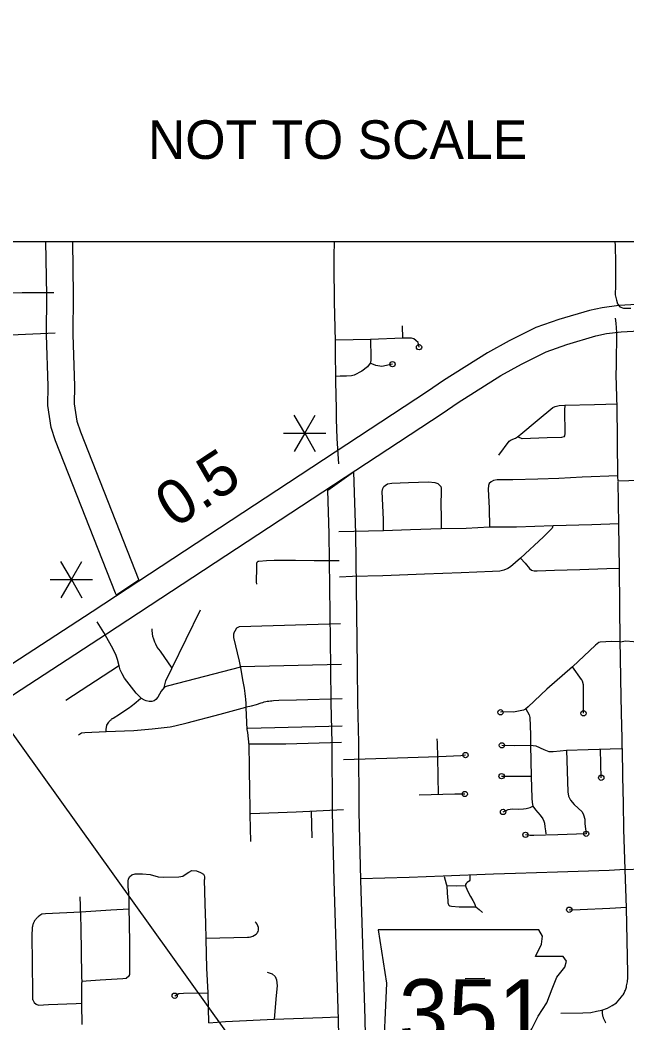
# Model space of a CAD drawing. Extents: x 309348 to 309445, y 336383 to 336484.
# Drawn here: x 309362.374 to 309364.99, y 336391.134 to 336395.46 of the extents above; entities that cross this region are included whole.
import ezdxf

# ---------------------------------------------------------------- set-up
doc = ezdxf.new("R2010")
doc.units = 0
doc.layers.add('R_Annotation', color=7, linetype='Continuous')
doc.layers.add('R_Border Notes', color=7, linetype='Continuous')

msp = doc.modelspace()

# ---------------------------------------------------------------- linework, layer by layer
at = {"layer": 'R_Annotation'}
for p, q in [((309363.601, 336393.6776), (309363.5555, 336393.7564)), ((309363.601, 336393.6776), (309363.6465, 336393.7564)), ((309363.5101, 336393.6776), (309363.601, 336393.6776)), ((309363.601, 336393.6776), (309363.5555, 336393.5989)), ((309363.601, 336393.6776), (309363.6919, 336393.6776)), ((309363.601, 336393.6776), (309363.6465, 336393.5989)), ((309362.5952, 336393.0464), (309362.5497, 336393.1252)), ((309362.5952, 336393.0464), (309362.6407, 336393.1252)), ((309362.5043, 336393.0464), (309362.5952, 336393.0464)), ((309362.5952, 336393.0464), (309362.5497, 336392.9677)), ((309362.5952, 336393.0464), (309362.6862, 336393.0464)), ((309362.5952, 336393.0464), (309362.6407, 336392.9677)), ((309362.8855, 336393.044), (309362.7898, 336392.9797))]:
    msp.add_line(p, q, dxfattribs=at)
for points in [[(309357.367, 336395.4603), (309360.1377, 336395.4603), (309363.8212, 336390.3132)], [(309362.7898, 336392.9797), (309362.7852, 336392.9884), (309362.5272, 336393.6448), (309362.5079, 336393.7026), (309362.4937, 336393.7978), (309362.4949, 336393.8807), (309362.4886, 336394.1021), (309362.4899, 336394.2732), (309362.4858, 336394.5049)], [(309362.5995, 336394.5049), (309362.6036, 336394.2737), (309362.6023, 336394.1033), (309362.6086, 336393.8815), (309362.6075, 336393.8054), (309362.6189, 336393.7292), (309362.6341, 336393.6835), (309362.8855, 336393.044)], [(309363.7324, 336394.1322), (309363.73, 336394.2449), (309363.7285, 336394.4017), (309363.7284, 336394.4416), (309363.7299, 336394.5049)], [(309364.9374, 336394.5049), (309364.9388, 336394.4861), (309364.941, 336394.414), (309364.9403, 336394.3153), (309364.9396, 336394.2748), (309364.9447, 336394.2513), (309364.9491, 336394.2358), (309364.9587, 336394.2233), (309364.9756, 336394.2174), (309364.983, 336394.2167), (309365.0066, 336394.2167)], [(309367.0035, 336394.3488), (309366.123, 336394.2935), (309364.9553, 336394.2289), (309364.883, 336394.2195), (309364.8281, 336394.2076), (309364.6962, 336394.1686), (309364.597, 336394.1336), (309364.4828, 336394.0765), (309364.3887, 336394.0246), (309364.2, 336393.9054), (309364.1306, 336393.8579), (309362.6846, 336392.9078), (309361.7768, 336392.3157)], [(309362.5204, 336394.2838), (309362.4556, 336394.2829), (309362.3833, 336394.2829), (309362.2884, 336394.2819), (309362.2282, 336394.2801)], [(309361.7768, 336392.3157), (309361.666, 336392.1041), (309361.7366, 336392.1538), (309362.7468, 336392.8127), (309364.194, 336393.7635), (309364.2625, 336393.8105), (309364.4466, 336393.9267), (309364.5357, 336393.9759), (309364.6415, 336394.0288), (309364.7313, 336394.0604), (309364.8563, 336394.0974), (309364.9024, 336394.1074), (309364.9658, 336394.1157), (309366.1297, 336394.18), (309367.0106, 336394.2353)], [(309364.9473, 336393.8005), (309364.947, 336393.8217), (309364.9444, 336393.8959), (309364.9439, 336393.9171), (309364.944, 336393.9382), (309364.9447, 336393.9594), (309364.9456, 336393.9941), (309364.9469, 336394.0917), (309364.9465, 336394.1122), (309364.9455, 336394.1327), (309364.9437, 336394.1532), (309364.9412, 336394.1736)], [(309362.2369, 336394.098), (309362.5256, 336394.1104)], [(309363.7332, 336394.0731), (309363.7324, 336394.1322)], [(309364.0246, 336394.088), (309364.023, 336394.1406)], [(309363.7354, 336393.9167), (309363.7338, 336394.0257), (309363.7332, 336394.0731)], [(309364.0938, 336394.049), (309364.0894, 336394.0689), (309364.0807, 336394.0782), (309364.0719, 336394.0845), (309364.0617, 336394.0875), (309364.0246, 336394.088), (309363.8849, 336394.0821), (309363.7349, 336394.0792)], [(309363.8849, 336394.0821), (309363.8859, 336394.0047), (309363.8859, 336393.993), (309363.8844, 336393.9837), (309363.8829, 336393.9803), (309363.8713, 336393.9642), (309363.8474, 336393.9457), (309363.8143, 336393.9282), (309363.8031, 336393.9258), (309363.7812, 336393.9243), (309363.7544, 336393.9238), (309363.7364, 336393.9233)], [(309363.9794, 336393.9759), (309363.9328, 336393.966), (309363.9082, 336393.9694), (309363.8829, 336393.9803)], [(309363.7479, 336393.5461), (309363.7407, 336393.6545), (309363.7378, 336393.7384), (309363.7374, 336393.7833), (309363.7357, 336393.9013), (309363.7354, 336393.9167)], [(309364.4373, 336393.5828), (309364.4825, 336393.6443), (309364.4907, 336393.6493), (309364.5095, 336393.6568), (309364.5189, 336393.6625), (309364.5321, 336393.6738), (309364.6037, 336393.7334), (309364.6708, 336393.7887), (309364.6802, 336393.7937), (309364.6972, 336393.7975), (309364.7223, 336393.7987), (309364.8504, 336393.8019), (309364.9473, 336393.8044)], [(309364.7223, 336393.7987), (309364.721, 336393.778), (309364.7229, 336393.6763), (309364.7204, 336393.6663), (309364.7179, 336393.6625), (309364.7079, 336393.66), (309364.6457, 336393.6575), (309364.5384, 336393.6543), (309364.5321, 336393.6562), (309364.5277, 336393.6581), (309364.5189, 336393.6625)], [(309364.9512, 336393.4911), (309364.9473, 336393.8005)], [(309363.9411, 336393.257), (309363.94, 336393.3055), (309363.9353, 336393.4263), (309363.9372, 336393.4394), (309363.9418, 336393.4478), (309363.9484, 336393.4529), (309363.9581, 336393.459), (309363.9773, 336393.4618), (309364.0482, 336393.465), (309364.1345, 336393.4678), (309364.162, 336393.466), (309364.1746, 336393.4604), (309364.1811, 336393.4552), (309364.1872, 336393.4478), (309364.189, 336393.4408), (309364.1886, 336393.4235), (309364.1876, 336393.3731), (309364.1886, 336393.3139), (309364.1896, 336393.2654)], [(309364.9511, 336393.4936), (309364.797, 336393.488), (309364.6959, 336393.4831), (309364.6066, 336393.4803), (309364.4978, 336393.4775), (309364.4308, 336393.4768), (309364.4148, 336393.474), (309364.4043, 336393.4684), (309364.3966, 336393.4608), (309364.3931, 336393.4517), (309364.3924, 336393.437), (309364.3959, 336393.354), (309364.398, 336393.2724)], [(309364.9516, 336393.4717), (309364.9512, 336393.4911)], [(309365.0903, 336393.4752), (309364.9516, 336393.4717)], [(309364.9545, 336393.284), (309364.9516, 336393.4688)], [(309364.9545, 336393.287), (309364.8382, 336393.2829), (309364.6722, 336393.2787), (309364.5138, 336393.2724), (309364.398, 336393.2724), (309364.2976, 336393.2675), (309364.1887, 336393.2654), (309364.0576, 336393.2612), (309363.9411, 336393.257), (309363.7485, 336393.2521)], [(309364.6703, 336393.2786), (309364.6677, 336393.2686), (309364.6301, 336393.2315), (309364.5319, 336393.1394), (309364.4881, 336393.1008), (309364.4773, 336393.0936), (309364.4593, 336393.0869), (309364.4423, 336393.0828), (309364.4099, 336393.0808), (309364.2761, 336393.0756), (309364.1172, 336393.07), (309363.9371, 336393.0633), (309363.8064, 336393.0592), (309363.7513, 336393.0571)], [(309364.9585, 336393.0926), (309364.9545, 336393.284)], [(309363.7503, 336393.1278), (309363.6419, 336393.1273), (309363.5617, 336393.1283), (309363.5351, 336393.1288), (309363.5025, 336393.129), (309363.4699, 336393.1285), (309363.4366, 336393.1272), (309363.4033, 336393.1251), (309363.4029, 336393.1251), (309363.4025, 336393.125), (309363.4021, 336393.1249), (309363.4017, 336393.1249), (309363.4013, 336393.1248), (309363.4009, 336393.1246), (309363.4006, 336393.1245), (309363.4002, 336393.1244), (309363.3998, 336393.1242), (309363.3995, 336393.1241), (309363.3991, 336393.1239), (309363.3987, 336393.1237), (309363.3984, 336393.1235), (309363.3981, 336393.1233), (309363.3977, 336393.1231), (309363.3974, 336393.1228), (309363.3971, 336393.1226), (309363.3968, 336393.1223), (309363.3965, 336393.1221), (309363.3962, 336393.1218), (309363.3959, 336393.1215), (309363.3957, 336393.1212), (309363.3954, 336393.1209), (309363.3952, 336393.1206), (309363.3949, 336393.1203), (309363.3947, 336393.1199), (309363.3945, 336393.1196), (309363.3943, 336393.1193), (309363.3941, 336393.1189), (309363.3939, 336393.1185), (309363.3938, 336393.1182), (309363.3936, 336393.1178), (309363.3935, 336393.1174), (309363.3933, 336393.1171), (309363.3932, 336393.1167), (309363.3931, 336393.1163), (309363.393, 336393.1159), (309363.393, 336393.1155), (309363.3929, 336393.1151), (309363.3929, 336393.1147), (309363.3928, 336393.1143), (309363.3928, 336393.1139), (309363.3928, 336393.1135), (309363.3928, 336393.1131), (309363.3928, 336393.1127), (309363.3929, 336393.1123), (309363.3929, 336393.1119), (309363.393, 336393.1115), (309363.393, 336393.1112), (309363.393, 336393.0834), (309363.3919, 336393.0522), (309363.3917, 336393.0486), (309363.3917, 336393.045), (309363.3918, 336393.0414), (309363.3921, 336393.0378), (309363.3924, 336393.0342), (309363.3929, 336393.0307), (309363.3935, 336393.0271)], [(309364.5319, 336393.1394), (309364.5509, 336393.1173), (309364.5699, 336393.0941), (309364.5782, 336393.0875), (309364.5895, 336393.0849), (309364.6034, 336393.0844), (309364.6775, 336393.0875), (309364.787, 336393.09), (309364.9028, 336393.0941), (309364.9584, 336393.0962)], [(309364.9615, 336392.7783), (309364.9585, 336393.0926)], [(309363.0281, 336392.6627), (309363.1515, 336392.9165)], [(309362.9948, 336392.5808), (309362.9819, 336392.565), (309362.9679, 336392.5398), (309362.9596, 336392.5296), (309362.9519, 336392.5233), (309362.9417, 336392.5204), (309362.9306, 336392.5209), (309362.9175, 336392.5238), (309362.9098, 336392.5267), (309362.8981, 336392.534), (309362.8744, 336392.5567), (309362.8246, 336392.6211), (309362.8139, 336392.6395), (309362.8062, 336392.6565), (309362.8008, 336392.6749), (309362.7945, 336392.702), (309362.7868, 336392.7238), (309362.7684, 336392.7596), (309362.7355, 336392.8187), (309362.7068, 336392.8644)], [(309363.3264, 336392.6659), (309363.3197, 336392.6942), (309363.2957, 336392.7966), (309363.2955, 336392.7979), (309363.2953, 336392.7992), (309363.2951, 336392.8004), (309363.295, 336392.8017), (309363.2949, 336392.803), (309363.2949, 336392.8043), (309363.2949, 336392.8056), (309363.2949, 336392.8069), (309363.295, 336392.8081), (309363.2952, 336392.8094), (309363.2954, 336392.8107), (309363.2956, 336392.8119), (309363.2959, 336392.8132), (309363.2962, 336392.8144), (309363.2965, 336392.8157), (309363.2969, 336392.8169), (309363.2974, 336392.8181), (309363.2979, 336392.8193), (309363.2984, 336392.8205), (309363.2989, 336392.8216), (309363.2996, 336392.8227), (309363.3002, 336392.8239), (309363.3009, 336392.825), (309363.3084, 336392.8377), (309363.3196, 336392.8448), (309363.7559, 336392.8566)], [(309363.0292, 336392.6649), (309362.9788, 336392.7372), (309362.9654, 336392.7554), (309362.9589, 336392.7681), (309362.9547, 336392.777), (309362.9503, 336392.7891), (309362.9471, 336392.8014), (309362.945, 336392.8141), (309362.9441, 336392.8268), (309362.9442, 336392.8344)], [(309364.9615, 336392.7783), (309364.9237, 336392.78), (309364.8747, 336392.7769), (309364.8685, 336392.7745), (309364.8543, 336392.7633), (309364.7551, 336392.6698), (309364.6442, 336392.5731), (309364.5649, 336392.4969), (309364.5532, 336392.4876), (309364.5445, 336392.4832), (309364.5011, 336392.4752), (309364.451, 336392.4764), (309364.4448, 336392.4739)], [(309364.9615, 336392.7783), (309364.9856, 336392.7819), (309365.0184, 336392.78), (309365.0525, 336392.7732), (309365.0767, 336392.7695), (309365.1027, 336392.767), (309365.1316, 336392.7695), (309365.1993, 336392.772), (309365.3028, 336392.7769), (309365.4137, 336392.7807), (309365.4577, 336392.7825), (309365.4873, 336392.7848)], [(309364.9701, 336392.3172), (309364.969, 336392.3622), (309364.966, 336392.4698), (309364.9638, 336392.6173), (309364.9625, 336392.7127), (309364.9615, 336392.7783)], [(309362.5711, 336392.5257), (309362.799, 336392.6746)], [(309362.9948, 336392.5808), (309362.9979, 336392.5829), (309363.0017, 336392.5847), (309363.0056, 336392.5864), (309363.0102, 336392.5881), (309363.0149, 336392.5895), (309363.3254, 336392.6698)], [(309362.9948, 336392.5808), (309362.9994, 336392.5983), (309363.0028, 336392.6093), (309363.0281, 336392.6627)], [(309363.3249, 336392.6719), (309363.7595, 336392.6809)], [(309363.3489, 336392.4939), (309363.3483, 336392.5126), (309363.3472, 336392.5311), (309363.3463, 336392.5428), (309363.345, 336392.5544), (309363.3434, 336392.566), (309363.3414, 336392.5775), (309363.3362, 336392.6064), (309363.3264, 336392.6659)], [(309364.8028, 336392.4696), (309364.8027, 336392.5874), (309364.8026, 336392.5894), (309364.8024, 336392.5914), (309364.8022, 336392.5934), (309364.8019, 336392.5954), (309364.8015, 336392.5974), (309364.8011, 336392.5993), (309364.8005, 336392.6013), (309364.8, 336392.6032), (309364.7993, 336392.6052), (309364.7986, 336392.607), (309364.7979, 336392.6089), (309364.7971, 336392.6108), (309364.7962, 336392.6126), (309364.7952, 336392.6144), (309364.7942, 336392.6161), (309364.7551, 336392.6698)], [(309362.7454, 336392.3904), (309362.7453, 336392.3932), (309362.7452, 336392.396), (309362.7453, 336392.3988), (309362.7455, 336392.4016), (309362.7458, 336392.4044), (309362.7461, 336392.4072), (309362.7466, 336392.4099), (309362.7472, 336392.4127), (309362.7478, 336392.4154), (309362.7486, 336392.4181), (309362.7568, 336392.4319), (309362.7583, 336392.4337), (309362.7598, 336392.4355), (309362.7613, 336392.4372), (309362.763, 336392.4389), (309362.7646, 336392.4405), (309362.7664, 336392.4421), (309362.7681, 336392.4436), (309362.7699, 336392.4451), (309362.7718, 336392.4465), (309362.7737, 336392.4478), (309362.7757, 336392.4491), (309362.8023, 336392.466), (309362.8389, 336392.4907), (309362.8458, 336392.4953), (309362.8526, 336392.5002), (309362.8592, 336392.5053), (309362.8657, 336392.5105), (309362.8932, 336392.5336)], [(309363.3488, 336392.4971), (309363.3716, 336392.5025), (309363.3929, 336392.5083), (309363.4141, 336392.5149), (309363.4204, 336392.5169), (309363.4268, 336392.5186), (309363.4333, 336392.5202), (309363.4398, 336392.5215), (309363.4463, 336392.5226), (309363.4529, 336392.5234), (309363.4595, 336392.5241), (309363.4661, 336392.5245), (309363.4901, 336392.5256), (309363.5656, 336392.5273), (309363.7624, 336392.5328)], [(309362.6256, 336392.3762), (309362.6391, 336392.3849), (309362.6532, 336392.3863), (309362.7454, 336392.3904), (309362.8643, 336392.396), (309362.9441, 336392.4023), (309363.0206, 336392.411), (309363.0419, 336392.4149), (309363.0937, 336392.429), (309363.236, 336392.4662), (309363.3479, 336392.4963)], [(309363.3537, 336392.4003), (309363.3489, 336392.4939)], [(309364.554, 336392.4882), (309364.5687, 336392.4634), (309364.5711, 336392.4517), (309364.5736, 336392.3786), (309364.5736, 336392.3321)], [(309363.3614, 336392.3328), (309363.3584, 336392.3593), (309363.3555, 336392.3873), (309363.3537, 336392.4003)], [(309363.7626, 336392.414), (309363.3553, 336392.4043)], [(309363.363, 336392.3374), (309363.5202, 336392.3385), (309363.7596, 336392.3451)], [(309364.1748, 336392.2791), (309364.1728, 336392.3426), (309364.1723, 336392.3599)], [(309363.3666, 336392.0318), (309363.3652, 336392.167), (309363.3633, 336392.1967), (309363.3625, 336392.2398), (309363.3614, 336392.3328)], [(309364.451, 336392.3315), (309364.5042, 336392.3302), (309364.5736, 336392.3321)], [(309364.7297, 336392.3104), (309364.7353, 336392.1307), (309364.7384, 336392.1127), (309364.7465, 336392.0954), (309364.7632, 336392.0756), (309364.7966, 336392.044), (309364.8028, 336392.0316), (309364.8078, 336392.0124), (309364.809, 336391.9925), (309364.814, 336391.9498), (309364.7731, 336391.9479), (309364.6926, 336391.9454), (309364.6387, 336391.9442), (309364.5885, 336391.9423), (309364.5711, 336391.943), (309364.5526, 336391.9454)], [(309364.5736, 336392.3321), (309364.5767, 336392.197), (309364.5798, 336392.1034), (309364.5811, 336392.0849), (309364.5848, 336392.0687), (309364.5959, 336392.0533), (309364.6157, 336392.0303), (309364.6275, 336392.0142), (309364.6319, 336392.0049), (309364.6343, 336391.995), (309364.6368, 336391.9795), (309364.6393, 336391.9628), (309364.6405, 336391.9498)], [(309364.5736, 336392.3321), (309364.5978, 336392.3296), (309364.6325, 336392.3135), (309364.6529, 336392.3054), (309364.6727, 336392.3042), (309364.7025, 336392.3073), (309364.7297, 336392.3104), (309364.8227, 336392.3141), (309364.9181, 336392.3166), (309364.9701, 336392.3172)], [(309364.8794, 336392.1917), (309364.8775, 336392.2517), (309364.8755, 336392.3155)], [(309364.9821, 336391.7964), (309364.9772, 336391.9692), (309364.975, 336392.082), (309364.9728, 336392.1954), (309364.9703, 336392.3172)], [(309364.2942, 336392.2893), (309364.2743, 336392.2855), (309364.179, 336392.2821), (309364.0015, 336392.2766), (309363.7678, 336392.2691)], [(309364.1779, 336392.1184), (309364.1748, 336392.2791)], [(309364.4497, 336392.1983), (309364.4999, 336392.1983), (309364.5767, 336392.1983)], [(309364.2911, 336392.1214), (309364.2482, 336392.1203), (309364.094, 336392.1162)], [(309363.7688, 336392.053), (309363.5642, 336392.0436), (309363.3689, 336392.0359)], [(309363.6292, 336392.0466), (309363.6313, 336391.9319)], [(309364.4559, 336392.044), (309364.4776, 336392.0545), (309364.4956, 336392.057), (309364.5241, 336392.0557), (309364.5439, 336392.057), (309364.5557, 336392.0588), (309364.573, 336392.0638), (309364.5848, 336392.0687)], [(309363.3685, 336391.9172), (309363.3666, 336392.0318)], [(309364.9821, 336391.7964), (309365.4048, 336391.8127), (309365.5358, 336391.8177), (309365.6977, 336391.8271), (309365.8166, 336391.8299), (309365.9383, 336391.8371), (309366.0872, 336391.8428), (309366.2613, 336391.8521), (309366.322, 336391.8539)], [(309362.8465, 336391.7641), (309362.8562, 336391.7729), (309362.8696, 336391.7768), (309362.902, 336391.7774), (309362.9344, 336391.7735), (309362.9696, 336391.764), (309362.9942, 336391.7623), (309363.0585, 336391.764), (309363.0759, 336391.7673), (309363.0859, 336391.7746), (309363.1016, 336391.7846), (309363.1144, 336391.7913), (309363.134, 336391.7902), (309363.1524, 336391.783), (309363.1642, 336391.7751), (309363.1681, 336391.7701), (309363.1692, 336391.7645), (309363.1694, 336391.7522)], [(309364.9821, 336391.7964), (309364.914, 336391.7918), (309364.6906, 336391.784), (309364.5101, 336391.7781), (309364.4146, 336391.7755), (309364.1977, 336391.7664), (309364.0509, 336391.7619), (309363.947, 336391.758), (309363.8413, 336391.7552)], [(309364.988, 336391.6301), (309364.9821, 336391.7964)], [(309362.8448, 336391.6196), (309362.8437, 336391.6677), (309362.8425, 336391.6959), (309362.8406, 336391.721), (309362.8396, 336391.7372), (309362.8396, 336391.74), (309362.84, 336391.7467), (309362.8417, 336391.7539), (309362.8445, 336391.7607), (309362.8465, 336391.7641)], [(309363.1757, 336391.4957), (309363.1754, 336391.5645), (309363.1722, 336391.6478), (309363.1694, 336391.7522)], [(309364.2025, 336391.7651), (309364.2112, 336391.7342), (309364.2137, 336391.7258), (309364.2158, 336391.6954), (309364.2168, 336391.6768), (309364.2174, 336391.6641), (309364.2177, 336391.6576), (309364.2183, 336391.6524), (309364.2199, 336391.6474), (309364.223, 336391.6415), (309364.2264, 336391.6394), (309364.2335, 336391.6378), (309364.267, 336391.6341), (309364.3386, 336391.6351)], [(309364.3131, 336391.7704), (309364.3134, 336391.7602), (309364.3134, 336391.7543), (309364.3134, 336391.7503), (309364.3106, 336391.7453), (309364.3069, 336391.7438), (309364.3007, 336391.7397), (309364.2976, 336391.7354), (309364.2948, 336391.7308), (309364.2936, 336391.7255), (309364.2951, 336391.7208), (309364.2998, 336391.7115), (309364.3063, 336391.6979), (309364.3159, 336391.679), (309364.3255, 336391.662), (309364.3332, 336391.6487), (309364.3354, 336391.6409), (309364.3386, 336391.6351)], [(309364.2927, 336391.7252), (309364.2539, 336391.7242), (309364.2143, 336391.7255)], [(309362.6345, 336391.6103), (309362.6341, 336391.6385), (309362.6335, 336391.6782)], [(309362.8447, 336391.6242), (309362.7656, 336391.6203), (309362.6354, 336391.6119), (309362.4844, 336391.6052), (309362.4682, 336391.6024), (309362.4554, 336391.5939)], [(309362.6345, 336391.6103), (309362.6346, 336391.6007), (309362.6358, 336391.5391), (309362.6374, 336391.4436), (309362.6395, 336391.3361), (309362.6397, 336391.3083)], [(309362.8434, 336391.3349), (309362.8439, 336391.3358), (309362.8444, 336391.3367), (309362.8449, 336391.3376), (309362.8453, 336391.3385), (309362.8457, 336391.3395), (309362.846, 336391.3404), (309362.8463, 336391.3414), (309362.8466, 336391.3424), (309362.8469, 336391.3433), (309362.8471, 336391.3443), (309362.8473, 336391.3453), (309362.8474, 336391.3463), (309362.8475, 336391.3473), (309362.8476, 336391.3484), (309362.8476, 336391.3494), (309362.8476, 336391.3504), (309362.8473, 336391.4658), (309362.8453, 336391.575), (309362.8448, 336391.6196)], [(309364.3386, 336391.6351), (309364.3528, 336391.6239), (309364.3673, 336391.6102)], [(309364.7413, 336391.6222), (309364.7887, 336391.6229), (309364.9166, 336391.6287), (309364.9879, 336391.6332)], [(309364.9672, 336391.2462), (309364.9711, 336391.2516), (309364.9738, 336391.2557), (309364.9776, 336391.2624), (309364.9796, 336391.2667), (309364.9814, 336391.271), (309364.9831, 336391.2753), (309364.9847, 336391.2797), (309364.9861, 336391.2842), (309364.9874, 336391.2887), (309364.9885, 336391.2932), (309364.9899, 336391.2992), (309364.9911, 336391.3052), (309364.9921, 336391.3113), (309364.9928, 336391.3174), (309364.9934, 336391.3235), (309364.9938, 336391.3296), (309364.994, 336391.3358), (309364.9939, 336391.3419), (309364.9937, 336391.3481), (309364.988, 336391.6301)], [(309362.4298, 336391.234), (309362.4278, 336391.4232), (309362.427, 336391.4803), (309362.427, 336391.5118), (309362.428, 336391.5432), (309362.4281, 336391.5455), (309362.4283, 336391.5478), (309362.4286, 336391.5501), (309362.429, 336391.5523), (309362.4295, 336391.5546), (309362.43, 336391.5568), (309362.4306, 336391.559), (309362.4313, 336391.5612), (309362.4321, 336391.5634), (309362.4329, 336391.5655), (309362.4338, 336391.5676), (309362.4348, 336391.5697), (309362.4358, 336391.5717), (309362.437, 336391.5737), (309362.4382, 336391.5757), (309362.4394, 336391.5776), (309362.4408, 336391.5794), (309362.4421, 336391.5813), (309362.4436, 336391.583), (309362.4451, 336391.5848), (309362.4467, 336391.5864), (309362.4483, 336391.588), (309362.45, 336391.5896), (309362.4517, 336391.5911), (309362.4535, 336391.5925), (309362.4554, 336391.5939), (309362.4573, 336391.5952)], [(309363.1757, 336391.4996), (309363.3548, 336391.5033), (309363.3611, 336391.5038), (309363.3693, 336391.5055), (309363.3772, 336391.5084), (309363.3846, 336391.5124), (309363.3914, 336391.5174), (309363.3956, 336391.5215), (309363.3972, 336391.5234), (309363.4, 336391.5281), (309363.4017, 336391.5334), (309363.4022, 336391.5388), (309363.4022, 336391.539), (309363.4015, 336391.5459), (309363.3995, 336391.5528), (309363.3963, 336391.5593), (309363.3921, 336391.5651), (309363.3915, 336391.5658), (309363.3879, 336391.5694)], [(309363.185, 336391.2636), (309363.1794, 336391.3707), (309363.1757, 336391.4957)], [(309363.4398, 336391.353), (309363.4604, 336391.3463), (309363.4733, 336391.334), (309363.4794, 336391.3194), (309363.4817, 336391.2932), (309363.4783, 336391.2523), (309363.4699, 336391.15)], [(309362.8434, 336391.3349), (309362.8321, 336391.3262), (309362.8176, 336391.324), (309362.7187, 336391.3184), (309362.6393, 336391.3128)], [(309362.6405, 336391.2155), (309362.6404, 336391.2263), (309362.6397, 336391.3083)], [(309364.3779, 336391.3256), (309364.292, 336391.3239)], [(309363.0406, 336391.2512), (309363.058, 336391.2607), (309363.0792, 336391.2618), (309363.185, 336391.2636)], [(309363.1879, 336391.1338), (309363.185, 336391.2636)], [(309362.4298, 336391.234), (309362.4352, 336391.2216), (309362.4442, 336391.2144), (309362.4542, 336391.2099), (309362.4973, 336391.2127), (309362.6164, 336391.2183), (309362.6393, 336391.2194)], [(309362.6415, 336391.1265), (309362.6405, 336391.2155)], [(309364.7044, 336391.176), (309364.7993, 336391.1769), (309364.8349, 336391.1789), (309364.8593, 336391.184), (309364.8822, 336391.1891), (309364.9061, 336391.1982), (309364.927, 336391.2094), (309364.9448, 336391.2211), (309364.9672, 336391.2462)], [(309364.8827, 336391.1858), (309364.8827, 336391.1827), (309364.8829, 336391.1796), (309364.8832, 336391.1766), (309364.8836, 336391.1736), (309364.8841, 336391.1705), (309364.8847, 336391.1675), (309364.8853, 336391.1645), (309364.8861, 336391.1616), (309364.887, 336391.1586), (309364.888, 336391.1557), (309364.8891, 336391.1529), (309364.8902, 336391.15), (309364.8915, 336391.1472), (309364.8929, 336391.1444), (309364.8944, 336391.1417), (309364.896, 336391.139), (309364.8977, 336391.1363), (309364.8994, 336391.1337)], [(309363.1879, 336391.1338), (309363.2603, 336391.14), (309363.4699, 336391.15), (309363.6773, 336391.1579), (309363.7459, 336391.1596)]]:
    msp.add_lwpolyline(points, dxfattribs=at)
for points in [[(309363.7003, 336393.4327), (309363.8117, 336393.5109), (309363.8195, 336393.2458), (309363.8278, 336392.6693), (309363.8281, 336392.5155), (309363.8332, 336392.3437), (309363.8347, 336392.0446), (309363.8414, 336391.7507), (309363.8599, 336391.1503), (309363.878, 336390.3143), (309363.7643, 336390.312), (309363.7462, 336391.1474), (309363.7278, 336391.7477), (309363.721, 336392.043), (309363.7195, 336392.3417), (309363.7144, 336392.5137), (309363.7142, 336392.6684), (309363.7058, 336393.2433)], [(309363.9184, 336391.5355), (309363.953, 336391.3047), (309363.9376, 336390.9547), (309363.9684, 336390.9355), (309364.0261, 336390.9355), (309364.0261, 336390.8124), (309364.5107, 336390.8124), (309364.5338, 336390.8624), (309364.5261, 336390.9432), (309364.5376, 336391.0355), (309364.5799, 336391.1085), (309364.6069, 336391.1624), (309364.6453, 336391.2201), (309364.6684, 336391.2816), (309364.6876, 336391.3316), (309364.7222, 336391.3739), (309364.7299, 336391.4009), (309364.7146, 336391.4201), (309364.5953, 336391.4201), (309364.6222, 336391.4739), (309364.6261, 336391.5086), (309364.6101, 336391.5351)]]:
    msp.add_lwpolyline(points, close=True, dxfattribs=at)
for centre in [(309364.0938, 336394.049), (309363.9794, 336393.9759), (309364.4448, 336392.4739), (309364.8028, 336392.4696), (309364.451, 336392.3315), (309364.2942, 336392.2893), (309364.4497, 336392.1983), (309364.8794, 336392.1917), (309364.2911, 336392.1214), (309364.4559, 336392.044), (309364.5526, 336391.9454), (309364.814, 336391.9498), (309364.7413, 336391.6222), (309363.0406, 336391.2512)]:
    msp.add_circle(centre, 0.0114, dxfattribs=at)
at = {"layer": 'R_Border Notes'}
msp.add_line((309354.7401, 336394.5049), (309372.2951, 336394.5049), dxfattribs=at)

# ---------------------------------------------------------------- texts
at = {"layer": 'R_Annotation'}
for s, height, p in [('NOT TO SCALE', 0.166667, (309362.9253, 336394.8612)), ('351', 0.28782, (309364.0063, 336391.0348))]:
    msp.add_text(s, height=height, dxfattribs=at).set_placement(p)
msp.add_text('0.5', height=0.19206, rotation=33.3048, dxfattribs=at).set_placement((309363.0409, 336393.2651))

doc.saveas('drawing.dxf')
